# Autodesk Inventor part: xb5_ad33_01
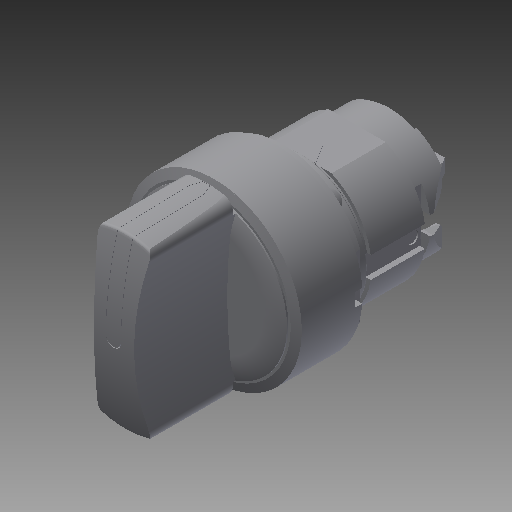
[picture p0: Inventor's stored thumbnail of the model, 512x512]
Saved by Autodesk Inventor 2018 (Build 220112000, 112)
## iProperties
Company: TraceParts S.A.
Created: 2018-05
Part Number: xb5_ad33_01
Checked By: TraceParts S.A.
Material: Generic
Catalog Web Link: www.traceparts.com
Document SubType Name: Modeling
Designer: TraceParts
Density: 1 g/cm^3
Appearance: Default
Author: TraceParts
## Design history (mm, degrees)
feature "xb5_ad33_01.ipt"
body "Solid1"
